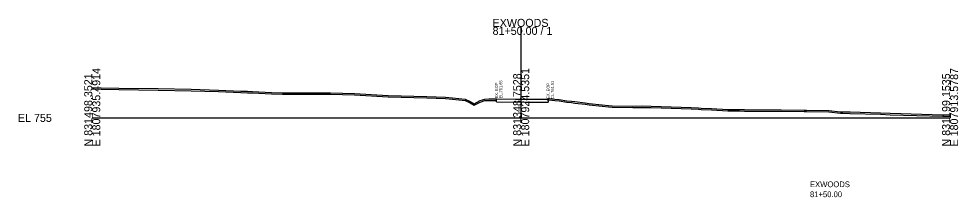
# Model space of a CAD drawing. Extents: x -26 to 303, y -29 to 2535.
# Drawn here: x -25.7 to 302.8, y 2472.2 to 2534.7 of the extents above; entities that cross this region are included whole.
import ezdxf

# ---------------------------------------------------------------- set-up
doc = ezdxf.new("R2010")
doc.units = 0
for name, color, linetype in [('DESIGN - SHEET - Light Grid', 7, 'Continuous'), ('DESIGN - TYPICAL - Bridge Deck Median Barriers', 7, 'Continuous'), ('SURVEY - AERIAL SURVEY - Mapping Setup - MAPPING LIMITS', 7, 'Continuous'), ('SURVEY - AERIAL SURVEY - Obscured Area', 7, 'Continuous'), ('SURVEY - AERIAL SURVEY - Out of collection Boundary Points', 7, 'Continuous'), ('SURVEY - AERIAL SURVEY - Skipped Points', 7, 'Continuous')]:
    doc.layers.add(name, color=color, linetype=linetype)

msp = doc.modelspace()

# ---------------------------------------------------------------- linework, layer by layer
at = {"layer": 'DESIGN - SHEET - Light Grid'}
for p, q in [((150, 2500), (150, 2531.88)), ((0, 2500), (150, 2500)), ((150, 2500), (300, 2500))]:
    msp.add_line(p, q, dxfattribs=at)
at = {"layer": 'SURVEY - AERIAL SURVEY - Mapping Setup - MAPPING LIMITS'}
msp.add_lwpolyline([(0, 2510.63), (3.16, 2510.56), (9.35, 2510.43), (23, 2510.27), (34.6, 2510.03), (44.1, 2509.74), (51.93, 2509.37), (54.3, 2509.31), (56.07, 2509.24), (62.68, 2508.9), (66.51, 2508.82), (83.37, 2508.79), (91.67, 2508.59), (103.43, 2507.9), (117.04, 2507.5), (123.48, 2507.25), (125.94, 2507.08), (130.4, 2506.6), (132.22, 2505.77), (133.57, 2504.96), (135.68, 2506.07), (137.33, 2506.6), (138.7, 2506.63), (141.37, 2506.65), (147.99, 2506.57), (149.97, 2506.58), (151.35, 2506.57), (159.41, 2506.51), (159.56, 2506.83), (161.79, 2506.62), (163.24, 2506.47), (166.02, 2506.03), (167.61, 2505.86), (168.79, 2505.7), (172.43, 2505.32), (173.8, 2505.08), (178.29, 2504.58), (180.55, 2504.35), (181.86, 2504.25), (189.03, 2504.17), (192.36, 2504.2), (195.41, 2504.17), (209.42, 2503.63), (211.98, 2503.53), (213, 2503.47), (216.52, 2503.29), (222.27, 2502.96), (226.35, 2502.93), (228.05, 2502.91), (240.96, 2502.81), (248.91, 2502.71), (249.84, 2502.7), (257.58, 2502.61), (261.66, 2502.11), (262.44, 2502.12), (265.06, 2502.1), (275.63, 2501.82), (279.08, 2501.62), (297.49, 2501.1), (300, 2501.04)], dxfattribs=at)
at = {"layer": 'SURVEY - AERIAL SURVEY - Obscured Area'}
for p, q in [((0, 2510.13), (3.16, 2510.06)), ((3.16, 2510.06), (9.35, 2509.93)), ((9.35, 2509.93), (23, 2509.77)), ((23, 2509.77), (34.6, 2509.53)), ((34.6, 2509.53), (44.1, 2509.24)), ((44.1, 2509.24), (51.93, 2508.87)), ((51.93, 2508.87), (54.3, 2508.81)), ((54.3, 2508.81), (56.07, 2508.74)), ((56.07, 2508.74), (62.68, 2508.4)), ((62.68, 2508.4), (66.51, 2508.32)), ((66.51, 2508.32), (83.37, 2508.29)), ((83.37, 2508.29), (91.67, 2508.09)), ((91.67, 2508.09), (103.43, 2507.4)), ((103.43, 2507.4), (117.04, 2507)), ((117.04, 2507), (123.48, 2506.75)), ((123.48, 2506.75), (125.94, 2506.58)), ((125.94, 2506.58), (130.4, 2506.1)), ((130.4, 2506.1), (132.22, 2505.27)), ((132.22, 2505.27), (133.57, 2504.46)), ((133.57, 2504.46), (135.68, 2505.57)), ((135.68, 2505.57), (137.33, 2506.1)), ((137.33, 2506.1), (138.7, 2506.13)), ((138.7, 2506.13), (141.37, 2506.15)), ((141.37, 2506.15), (141.37, 2506.65)), ((159.41, 2506.01), (159.41, 2506.51)), ((159.41, 2506.01), (159.56, 2506.33)), ((159.56, 2506.33), (161.79, 2506.12)), ((161.79, 2506.12), (163.24, 2505.97)), ((163.24, 2505.97), (166.02, 2505.53)), ((166.02, 2505.53), (167.61, 2505.36)), ((167.61, 2505.36), (168.79, 2505.2)), ((168.79, 2505.2), (172.43, 2504.82)), ((172.43, 2504.82), (173.8, 2504.58)), ((173.8, 2504.58), (178.29, 2504.08)), ((178.29, 2504.08), (180.55, 2503.85)), ((180.55, 2503.85), (181.86, 2503.75)), ((181.86, 2503.75), (189.03, 2503.67)), ((189.03, 2503.67), (192.36, 2503.7)), ((192.36, 2503.7), (195.41, 2503.67)), ((195.41, 2503.67), (209.42, 2503.13)), ((209.42, 2503.13), (211.98, 2503.03)), ((211.98, 2503.03), (213, 2502.97)), ((213, 2502.97), (216.52, 2502.79)), ((216.52, 2502.79), (222.27, 2502.46)), ((222.27, 2502.46), (226.35, 2502.43)), ((226.35, 2502.43), (228.05, 2502.41)), ((228.05, 2502.41), (240.96, 2502.31)), ((240.96, 2502.31), (248.91, 2502.21)), ((248.91, 2502.21), (249.84, 2502.2)), ((249.84, 2502.2), (257.58, 2502.11)), ((257.58, 2502.11), (261.66, 2501.61)), ((261.66, 2501.61), (262.44, 2501.62)), ((262.44, 2501.62), (265.06, 2501.6)), ((265.06, 2501.6), (275.63, 2501.32)), ((275.63, 2501.32), (279.08, 2501.12)), ((279.08, 2501.12), (297.49, 2500.6)), ((297.49, 2500.6), (300, 2500.54))]:
    msp.add_line(p, q, dxfattribs=at)
at = {"layer": 'SURVEY - AERIAL SURVEY - Out of collection Boundary Points'}
for p, q in [((141.37, 2505.65), (141.37, 2506.65)), ((141.37, 2505.65), (147.99, 2505.57)), ((147.99, 2505.57), (149.97, 2505.58)), ((149.97, 2505.58), (151.35, 2505.57)), ((151.35, 2505.57), (159.41, 2505.51)), ((159.41, 2506.51), (159.41, 2505.51))]:
    msp.add_line(p, q, dxfattribs=at)

# ---------------------------------------------------------------- texts
at = {"layer": 'DESIGN - SHEET - Light Grid'}
for s, p in [('EXWOODS', (140, 2531.88)), ('81+50.00 / 1', (140, 2529.08)), ('EL 755', (-26, 2498.6))]:
    msp.add_text(s, height=2.8, dxfattribs=at).set_placement(p)
for s, p in [('E 1807935.4914', (2.8, 2490)), ('E 1807924.5351', (152.8, 2490)), ('E 1807913.5787', (302.8, 2490)), ('N 831498.3521', (0, 2490)), ('N 831348.7528', (150, 2490)), ('N 831199.1535', (300, 2490))]:
    msp.add_text(s, height=2.8, rotation=90, dxfattribs=at).set_placement(p)
at = {"layer": 'DESIGN - TYPICAL - Bridge Deck Median Barriers'}
for s, p in [('EXWOODS', (251, 2475.75)), ('81+50.00', (251, 2472.25))]:
    msp.add_text(s, height=2, dxfattribs=at).set_placement(p)
at = {"layer": 'SURVEY - AERIAL SURVEY - Skipped Points'}
for s, p in [('EX. EOP', (141.87, 2506.85)), ('EL.761.65', (143.37, 2506.85)), ('EX. EOP', (159.91, 2506.71)), ('EL.761.51', (161.41, 2506.71))]:
    msp.add_text(s, height=1, rotation=90, dxfattribs=at).set_placement(p)

doc.saveas('drawing.dxf')
